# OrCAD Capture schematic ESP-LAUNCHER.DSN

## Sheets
1 Sheet02_Interface: size A3
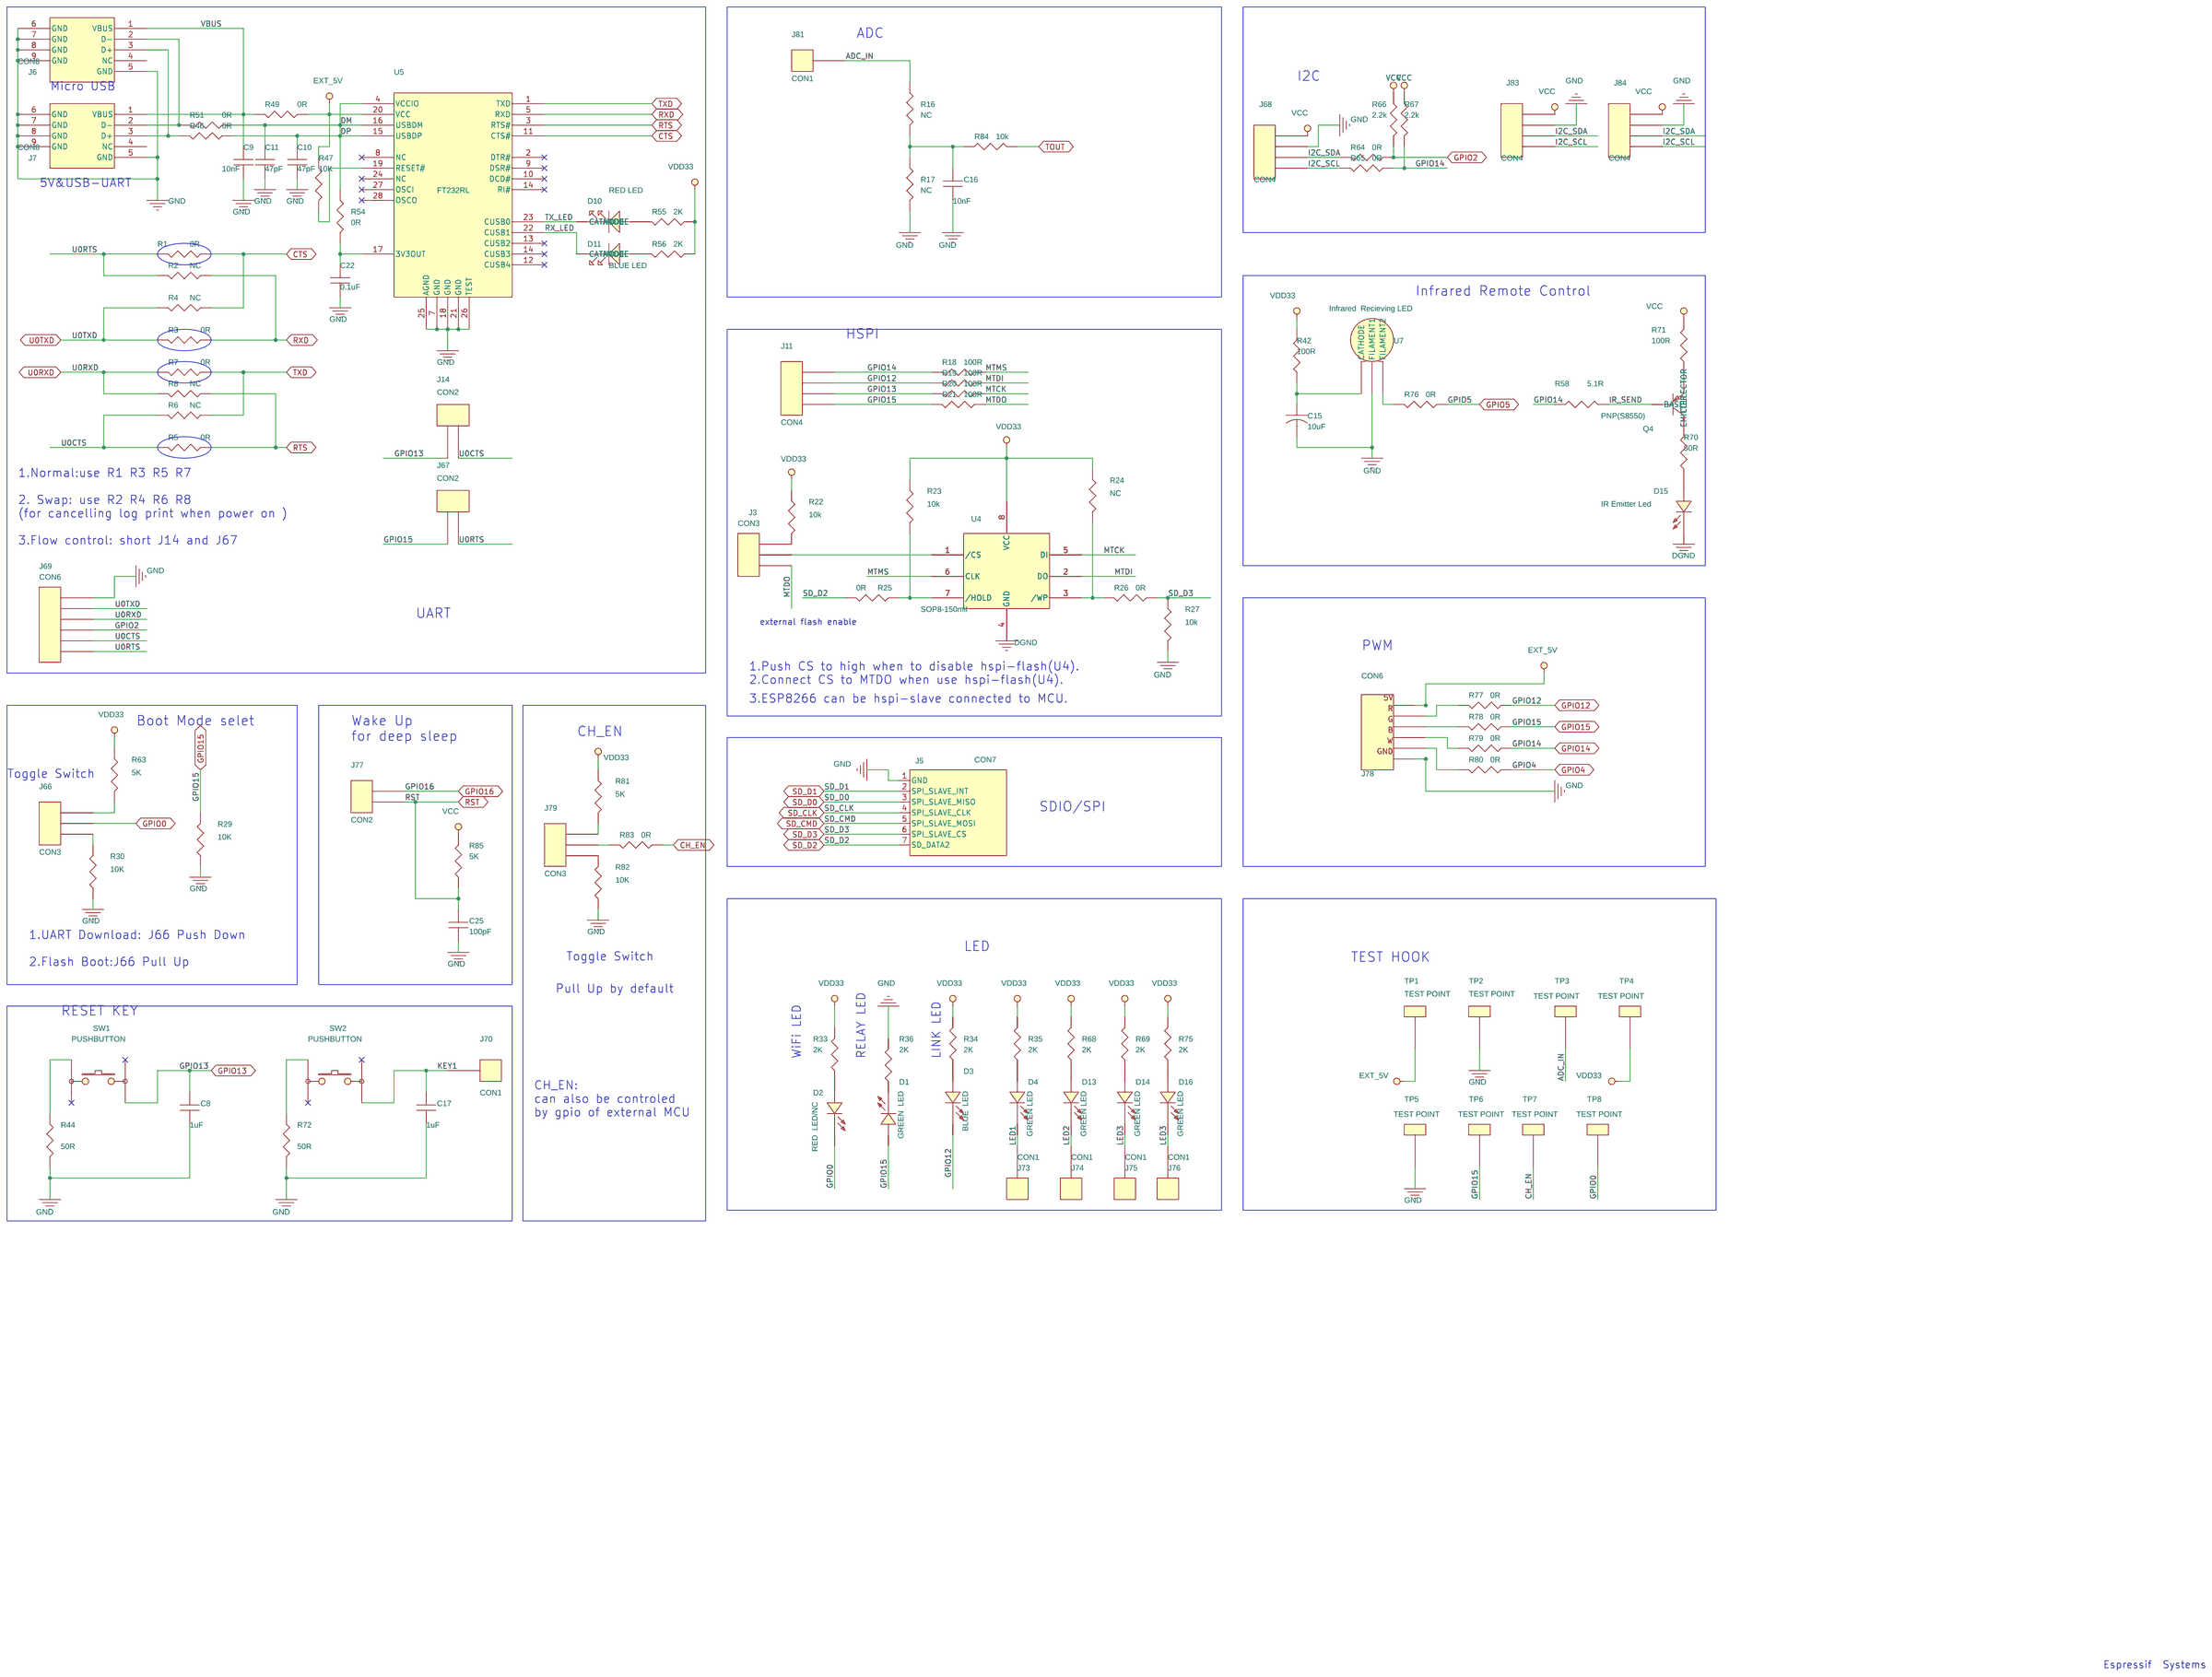
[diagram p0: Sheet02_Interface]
2 Sheet03_Power: size A3; title: ESP8266 Evaluation Board; rev: 1.0
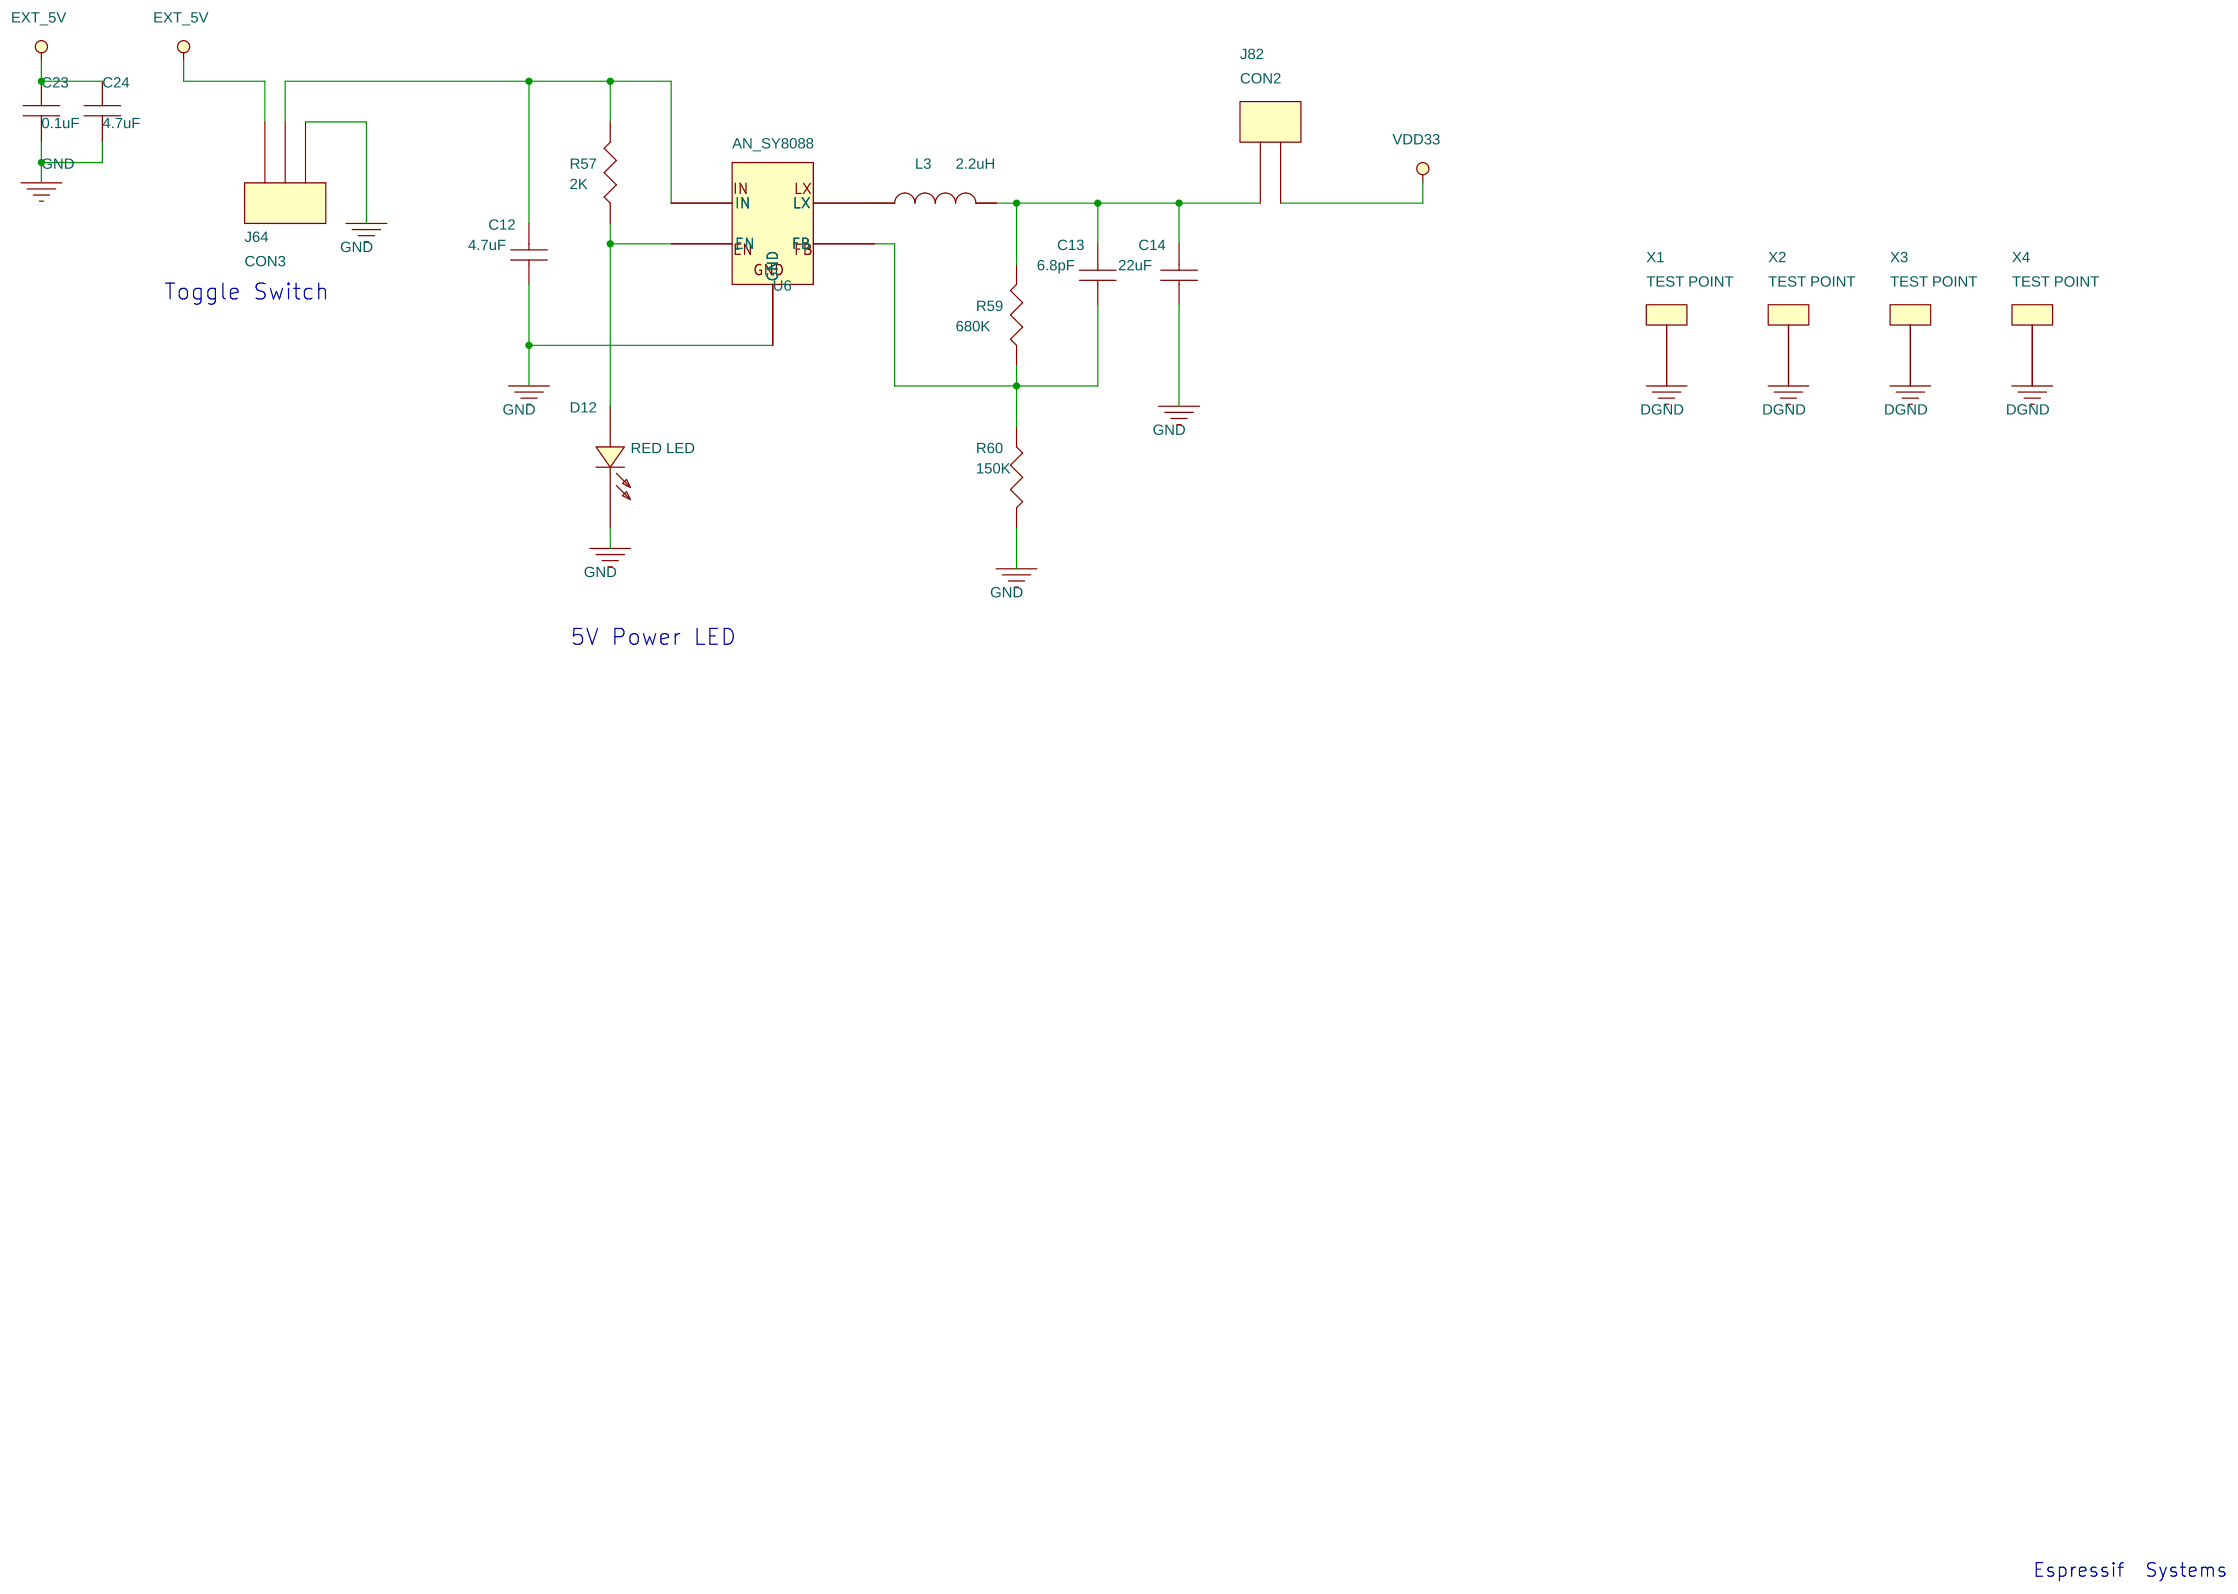
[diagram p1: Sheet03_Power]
3 Sheet04_TestBoard: size A3; title: ESP8266 Evaluation Board; rev: 1.0
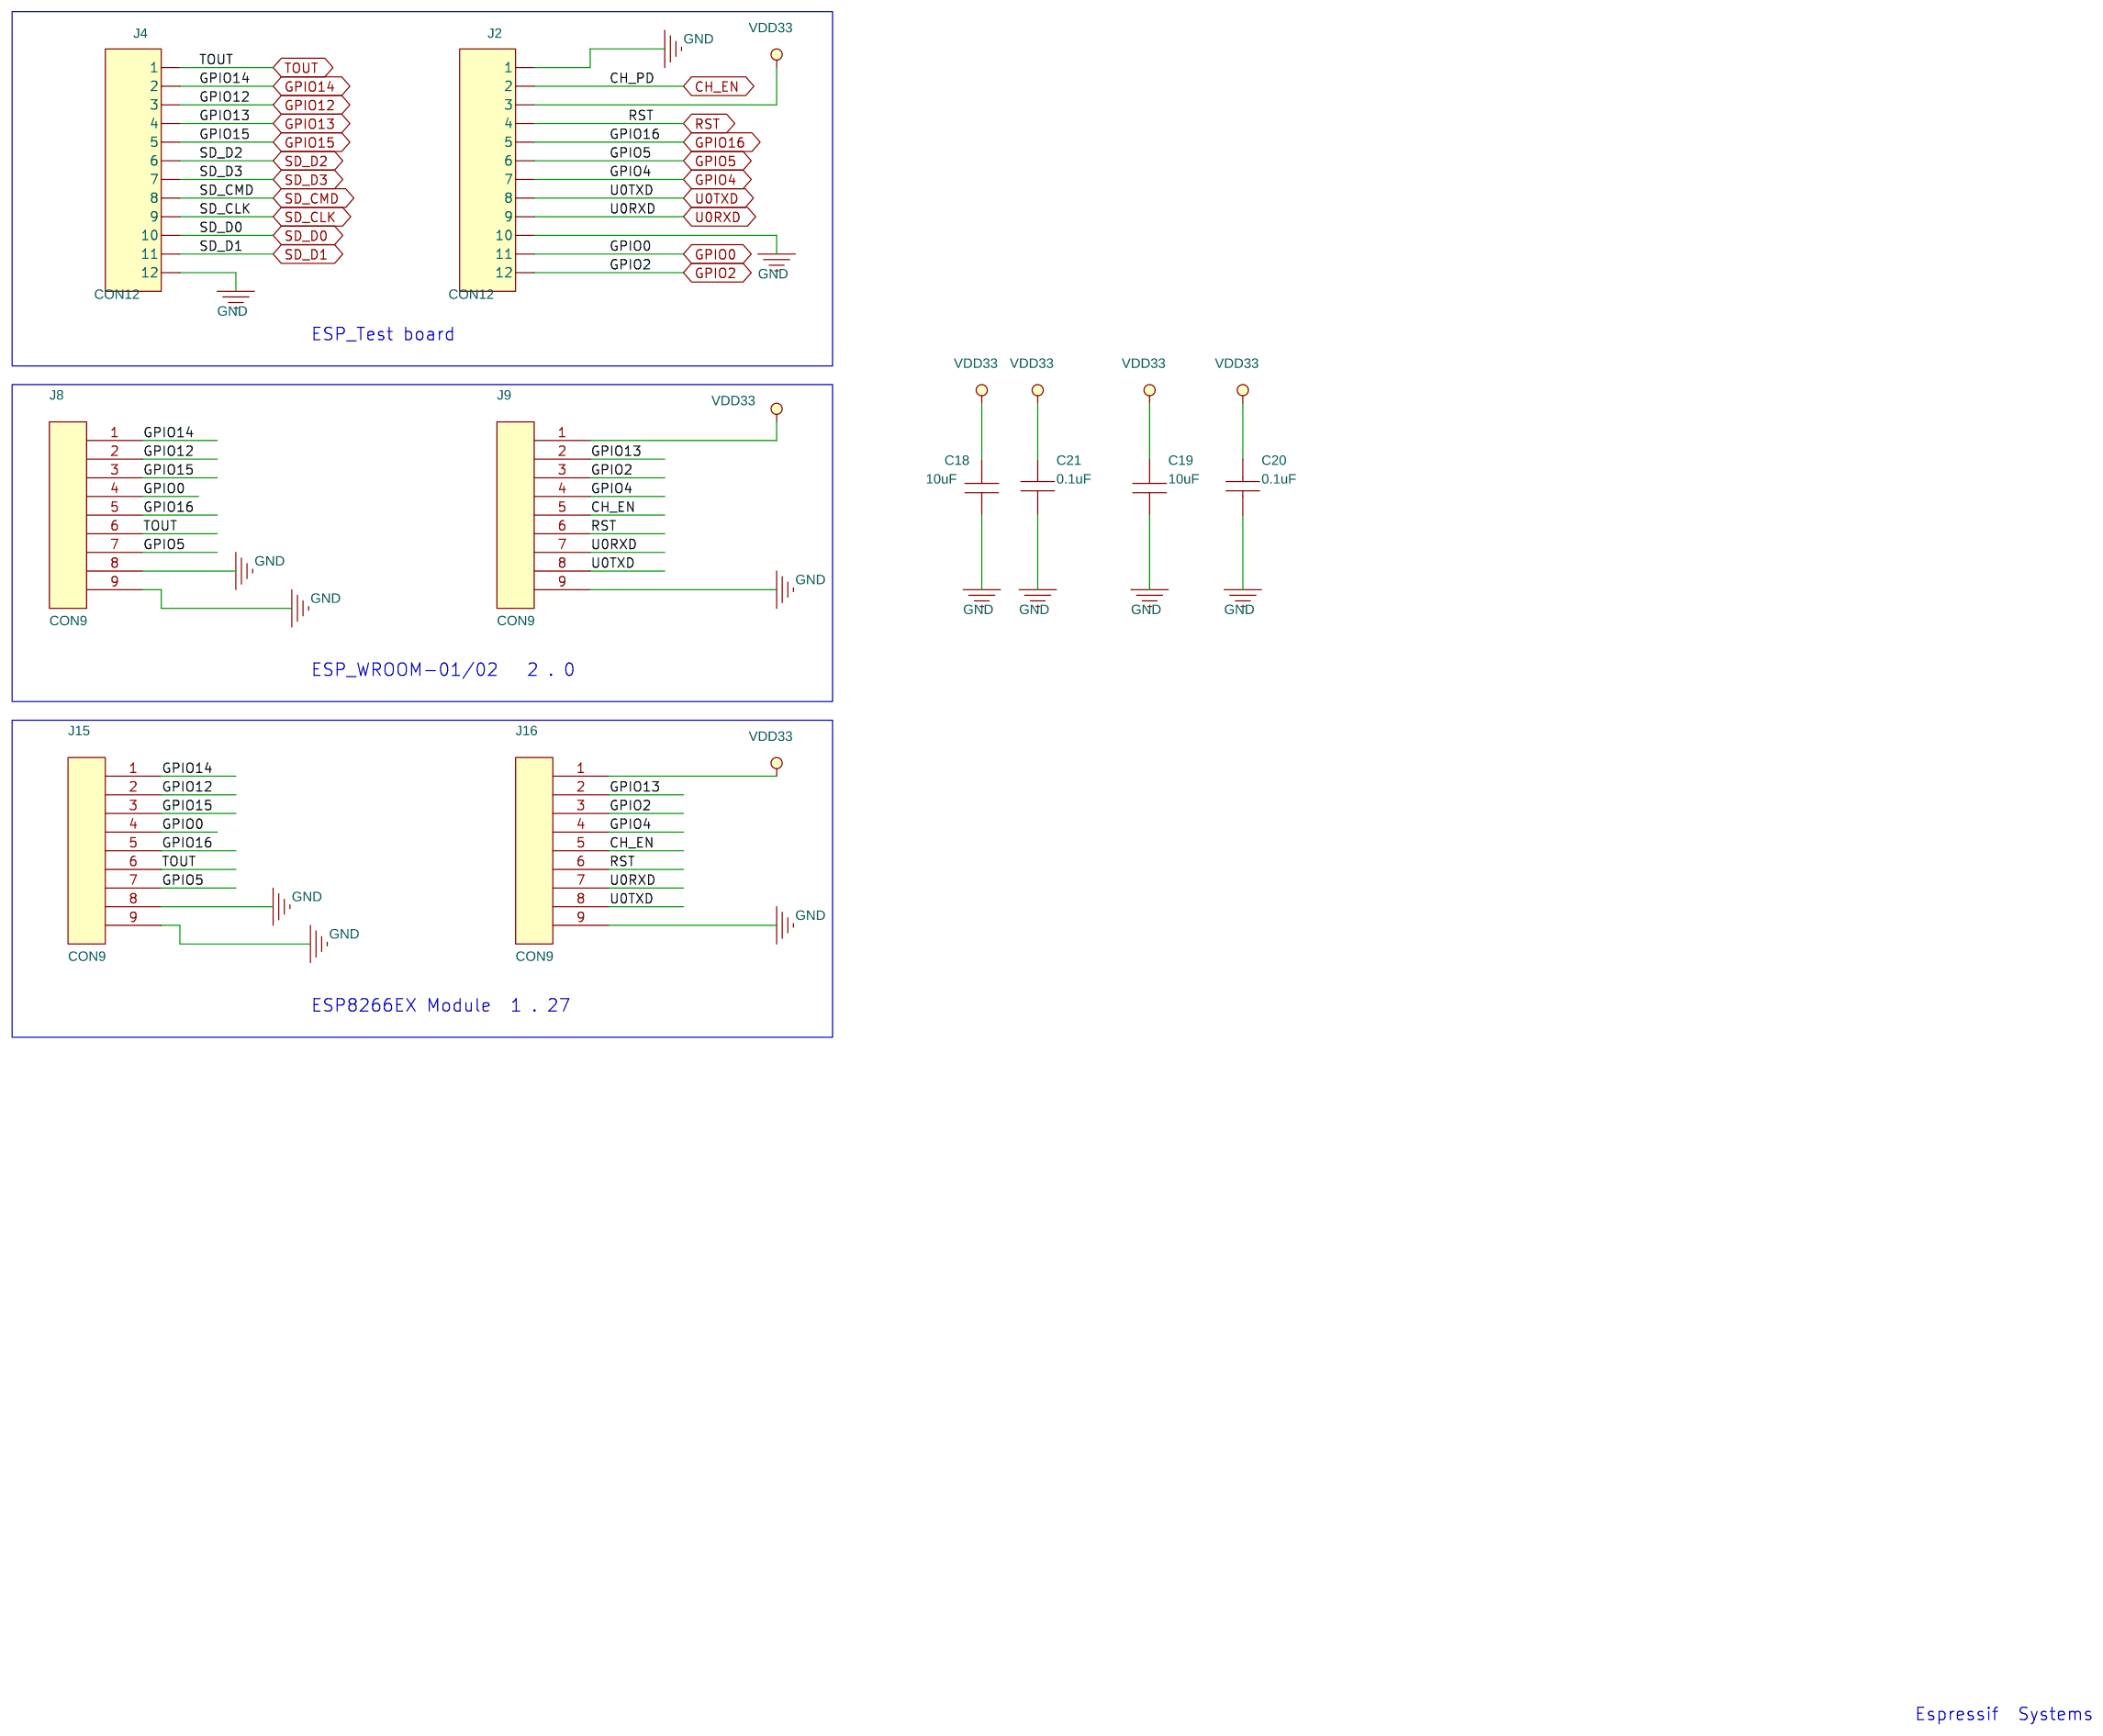
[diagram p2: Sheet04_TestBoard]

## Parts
sheet Sheet02_Interface
C8  1uF  [0603C]
C9  10nF  [0603C]
C10  47pF  [0603C]
C11  47pF  [0603C]
C15  10uF  [0603C]
C16  10nF  [0402A]
C17  1uF  [0603C]
C22  0.1uF  [0603C]
C25  100pF  [0603C]
D1  GREEN  LED  [0603D/A]
D2  RED  LED/NC  [0603D/A]
D3  BLUE  LED  [0603D/A]
D4  GREEN LED  [0603D/A]
D10  RED LED  [0603D/A]
D11  BLUE LED  [0603D/A]
D13  GREEN LED  [0603D/A]
D14  GREEN LED  [0603D/A]
D15  IR Emitter Led  [INFRARED_T]
D16  GREEN LED  [0603D/A]
J3  CON3  [CON3]
J5  CON7  [CON7]
J6  CON8  [MICRO_USB]
J7  CON8  [MICRO_USB]
J11  CON4
J14  CON2  [CON2]
J66  CON3  [MSK_01A1]
J67  CON2  [CON2]
J68  CON4  [CON4]
J69  CON6  [CON6]
J70  CON1  [1MM_VIAS]
J73  CON1  [1MM_VIAS]
J74  CON1  [1MM_VIAS]
J75  CON1  [1MM_VIAS]
J76  CON1  [1MM_VIAS]
J77  CON2  [CON2]
J78  CON6  [CON6]
J79  CON3  [MSK_01A1]
J81  CON1  [1MM_VIAS]
J83  CON4  [CON4_1.25]
J84  CON4  [CON4_1.25]
Q4  PNP(S8550)  [SOT-23-3]
R1  0R  [0402A]
R2  NC  [0402A]
R3  0R  [0402A]
R4  NC  [0402A]
R5  0R  [0402A]
R6  NC  [0402A]
R7  0R  [0402A]
R8  NC  [0402A]
R16  NC  [0603R]
R17  NC  [0603R]
R18  100R  [0402A]
R19  100R  [0402A]
R20  100R  [0402A]
R21  100R  [0402A]
R22  10k  [0402A]
R23  10k  [0402A]
R24  NC  [0402A]
R25  0R  [0402A]
R26  0R  [0402A]
R27  10k  [0402A]
R29  10K  [0402A]
R30  10K  [0603R]
R33  2K  [0402A]
R34  2K  [0402A]
R35  2K  [0402A]
R36  2K  [0402A]
R42  100R  [0402A]
R44  50R  [0603R]
R46  0R  [0603R]
R47  10K  [0603R]
R49  0R  [0603R]
R51  0R  [0603R]
R54  0R  [0603R]
R55  2K  [0603R]
R56  2K  [0603R]
R58  5.1R  [0402A]
R63  5K  [0603R]
R64  0R  [0402A]
R65  0R  [0402A]
R66  2.2k  [0402A]
R67  2.2k  [0402A]
R68  2K  [0402A]
R69  2K  [0402A]
R70  50R  [0603R]
R71  100R  [0603R]
R72  50R  [0603R]
R75  2K  [0402A]
R76  0R  [0402A]
R77  0R  [0402A]
R78  0R  [0402A]
R79  0R  [0402A]
R80  0R  [0402A]
R81  5K  [0603R]
R82  10K  [0603R]
R83  0R  [0402A]
R84  10k  [0402A]
R85  5K  [0603R]
SW1  PUSHBUTTON  [KEY_3x6x2.5]
SW2  PUSHBUTTON  [KEY_3x6x2.5]
TP1  TEST POINT
TP2  TEST POINT
TP3  TEST POINT
TP4  TEST POINT
TP5  TEST POINT
TP6  TEST POINT
TP7  TEST POINT
TP8  TEST POINT
U4  SOP8-150mil  [SOIC-8P]
U5  FT232RL  [FT232]
U7  Infrared  Recieving LED  [INFRARED_R]
sheet Sheet03_Power
C12  4.7uF  [0603C]
C13  6.8pF  [0603C]
C14  22uF  [0603C]
C23  0.1uF  [0603C]
C24  4.7uF  [0603C]
D12  RED LED  [0603D/A]
J64  CON3  [KG_2]
J82  CON2  [CON2]
L3  2.2uH  [L2520]
R57  2K  [0603R]
R59  680K  [0603R]
R60  150K  [0603R]
U6  AN_SY8088  [SOT23-5]
X1  TEST POINT  [1MM_VIAS]
X2  TEST POINT  [1MM_VIAS]
X3  TEST POINT  [1MM_VIAS]
X4  TEST POINT  [1MM_VIAS]
sheet Sheet04_TestBoard
C18  10uF  [0603C]
C19  10uF  [0603C]
C20  0.1uF  [0402A]
C21  0.1uF  [0402A]
J2  CON12
J4  CON12
J8  CON9  [CON9_2.0_NEW]
J9  CON9  [CON9_2.0_NEW]
J15  CON9  [CON9_1.27]
J16  CON9  [CON9_1.27]

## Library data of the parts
C8-C14 C16-C25 = CAP_NP
C15 = CAP
D1-D4 D13 D14 D16 = LED_5
D10 = LED_6
D11 = LED_4
D12 D15 = LED_1
J3 J64 J66 J79 = CON3
J5 = CON10_0
J6 J7 = CON4_9
J11 = CON4
J14 J67 J77 J82 = CON2
J68 J83 J84 = CON4_8
J69 = CON6_7
J70 J73-J76 J81 = CON1
J78 = CON6_6
Q4 = PNP_0
R1-R8 = RESISTOR_0: SIGNAL_MODEL: DEFAULT_RESISTOR_10000OHM_1_2
R16-R21 R44 R57 R59 R60 R63-R67 R72 R76-R81 R83-R85 = RESISTOR_0
R22-R27 R29 R30 R82 = R_0: P/N: 21-253-625101
R33-R36 R46 R47 R49 R51 R54-R56 R68 R69 R75 = RESISTOR_0: SIGNAL_MODEL: DEFAULT_RESISTOR_200OHM_1_2
R42 R58 R70 R71 = RESISTOR
SW1 SW2 = SW_PUSHBUTTON-SPST-2
TP1-TP8 X1-X4 = TEST_POINT
U4 = FLASH_1
U5 = SP232_1
U7 = TRIODE_1
L3 = INDUCTOR
U6 = CON5_0
J2 = CON12_1
J4 = CON12
J8 J9 J15 J16 = CON9_0

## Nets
GND: C8.2 C9.2 C10.2 C11.2 C12.1 C14.1 C15.2 C16.2 C17.2 C18.1 C19.1 C20.2 C21.2 C22.2 C23.2 C24.2 C25.2 D12.2(CATHODE) D15.2(CATHODE) J2.1 J2.10 J4.12 J5.1(GND) J6.5(GND) J6.6(GND) J6.7(GND) J6.8(GND) J6.9(GND) J7.5(GND) J7.6(GND) J7.7(GND) J7.8(GND) J7.9(GND) J8.8 J8.9 J9.9 J15.8 J15.9 J16.9 J64.1 J68.2 J69.1 J78.6 J83.2 J84.2 R17.2 R27.2 R29.1 R30.1 R36.2 R44.2 R60.1 R72.2 R82.1 TP2.1 TP5.1 U4.4(GND) U5.7(GND) U5.18(GND) U5.21(GND) U5.25(AGND) U5.26(TEST) U6.2(GND) U7.2(FILAMENT1) X1.1 X2.1 X3.1 X4.1
VBUS: C9.1 J6.1(VBUS) J7.1(VBUS) R49.2
VDD33: C18.2 C19.2 C20.1 C21.1 J2.3 J9.1 J16.1 J68.1 J82.2 J83.1 J84.1 R22.1 R23.1 R24.1 R33.2 R34.2 R35.2 R42.2 R55.1 R56.1 R63.1 R66.1 R67.1 R68.2 R69.2 R71.2 R75.2 R81.1 R85.2 TP4.1 U4.8(VCC)
ADC_IN: J81.1 R16.1 TP3.1
CH_EN: J2.2 J9.5 J16.5 R83.1 TP7.1
CTS: R1.1 R4.1 U5.11(CTS#)
DM: C11.1 R51.1 U5.16(USBDM)
DP: C10.1 R46.1 U5.15(USBDP)
EXT_5V: C23.1 C24.1 J64.3 J78.1 R47.1 R49.1 TP1.1 U5.20(VCC)
GPIO0: D2.2(CATHODE) J2.11 J8.4 J15.4 J66.2 TP8.1
GPIO2: J2.12 J9.3 J16.3 J69.4 R64.1 R66.2
GPIO4: J2.7 J9.4 J16.4 R80.1
GPIO5: J2.6 J8.7 J15.7 R76.1
GPIO12: D3.2(CATHODE) J4.3 J8.2 J11.2 J15.2 R19.2 R77.1
GPIO13: C8.1 J4.4 J9.2 J11.3 J14.1 J16.2 R20.2 SW1.3
GPIO14: J4.2 J8.1 J11.1 J15.1 R18.2 R58.1 R65.1 R67.2 R79.1
GPIO15: D1.1(ANODE) J4.5 J8.3 J11.4 J15.3 J67.1 R21.2 R29.2 R78.1 TP6.1
GPIO16: J2.5 J8.5 J15.5 J77.2
I2C_SCL: J68.4 J83.4 J84.4 R65.2
I2C_SDA: J68.3 J83.3 J84.3 R64.2
IR_SEND: Q4.1(BASE) R58.2
KEY1: C17.1 J70.1 SW2.3
LED1: D4.2(CATHODE) J73.1
LED2: D13.2(CATHODE) J74.1
LED3: D14.2(CATHODE) D16.2(CATHODE) J75.1 J76.1
MTCK: R20.1 U4.5(DI)
MTDI: R19.1 U4.2(DO)
MTDO: J3.3 R21.1
MTMS: R18.1 U4.6(CLK)
RST: C25.1 J2.4 J9.6 J16.6 J77.1 R85.1
RTS: R5.1 R8.1 U5.3(RTS#)
RX_LED: D11.2(CATHODE) U5.22(CUSB1)
RXD: R2.1 R3.1 U5.5(RXD)
SD_CLK: J4.9 J5.4(SPI_SLAVE_CLK)
SD_CMD: J4.8 J5.5(SPI_SLAVE_MOSI)
SD_D0: J4.10 J5.3(SPI_SLAVE_MISO)
SD_D1: J4.11 J5.2(SPI_SLAVE_INT)
SD_D2: J4.6 J5.7(SD_DATA2) R25.2
SD_D3: J4.7 J5.6(SPI_SLAVE_CS) R26.1 R27.1
TOUT: J4.1 J8.6 J15.6 R84.2
TX_LED: D10.2(CATHODE) U5.23(CUSB0)
TXD: R6.1 R7.1 U5.1(TXD)
U0CTS: J14.2 J69.5 R5.2 R6.2
U0RTS: J67.2 J69.6 R1.2 R2.2
U0RXD: J2.9 J9.7 J16.7 J69.3 R7.2 R8.2
U0TXD: J2.8 J9.8 J16.8 J69.2 R3.2 R4.2
N15805984: D12.1(ANODE) R57.2 U6.1(EN)
N15805992: C12.2 J64.2 R57.1 U6.4(IN)
N15806210: C13.1 R59.2 R60.2 U6.5(FB)
N15806214: C13.2 C14.2 J82.1 L3.1 R59.1
N15814601: R54.1 U5.4(VCCIO)
N15817179: R47.2 U5.19(RESET#)
N15818208: C22.1 R54.2 U5.17(3V3OUT)
N15904510: R44.1 SW1.1
N15904902: J66.1 R30.2
N15906126: R24.2 R26.2 U4.3(/WP)
N15906160: J3.2 U4.1(/CS)
N15906246: R23.2 R25.1 U4.7(/HOLD)
N15908619: C16.1 R16.2 R17.1 R84.1
N15941914: D1.2(CATHODE) R36.1
N15944907: R76.2 U7.3(FILAMENT2)
N15944911: C15.1 R42.1 U7.1(CATHODE)
N15945412: Q4.2(EMITTER) R71.1
N15945684: J78.4 R79.2
N15946727: R72.1 SW2.1
N15949583: J78.2 R77.2
N15949683: J78.5 R80.2
N15949855: J78.3 R78.2
N15951946: J79.2 R83.2
N15952135: J79.3 R81.2
N15961573: J66.3 R63.2
N15978899: J6.2(D-) J7.2(D-) R51.2
N15978912: J6.3(D+) J7.3(D+) R46.2
N16058039: L3.2 U6.3(LX)
N16058474: D4.1(ANODE) R35.1
N16058475: D10.1(ANODE) R55.2
N16058476: D16.1(ANODE) R75.1
N16058478: J79.1 R82.2
N16058479: Q4.3(COLLECTOR) R70.2
N16058480: D15.1(ANODE) R70.1
N16058481: D2.1(ANODE) R33.1
N16058482: J3.1 R22.2
N16058483: D14.1(ANODE) R69.1
N16058484: D13.1(ANODE) R68.1
N16058485: D11.1(ANODE) R56.2
N16058486: D3.1(ANODE) R34.1

Not connected (* = marked no-connect by the designer): J6 4(NC); J7 4(NC); SW1 2* 4*; SW2 2* 4*; U5 2(DTR#)* 8(NC)* 9(DSR#)* 10(DCD#)* 12(CUSB4)* 13(CUSB2)* 14(RI#)* 24(NC)* 27(OSCI)* 28(OSCO)*

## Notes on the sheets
sheet 1
- ADC
- I2C
- Micro USB
- 5V&USB-UART
- Infrared Remote Control
- HSPI
- 1.Normal:use R1 R3 R5 R7
  2. Swap: use R2 R4 R6 R8
  (for cancelling log print when power on )
  3.Flow control: short J14 and J67
- UART
- external flash enable
- PWM
- 1.Push CS to high when to disable hspi-flash(U4).
  2.Connect CS to MTDO when use hspi-flash(U4).
- 3.ESP8266 can be hspi-slave connected to MCU.
- Boot Mode selet
- Wake Up
  for deep sleep
- CH_EN
- Toggle Switch
- SDIO/SPI
- 1.UART Download: J66 Push Down
  2.Flash Boot:J66 Pull Up
- Toggle Switch
- LED
- TEST HOOK
- Pull Up by default
- RESET KEY
- WiFi LED
- RELAY LED
- LINK LED
- CH_EN:
  can also be controled
  by gpio of external MCU
- Espressif  Systems
sheet 2
- Toggle Switch
- 5V Power LED
- Espressif  Systems
sheet 3
- ESP_Test board
- ESP_WROOM-01/02   2 . 0
- ESP8266EX Module  1 . 27
- Espressif  Systems
